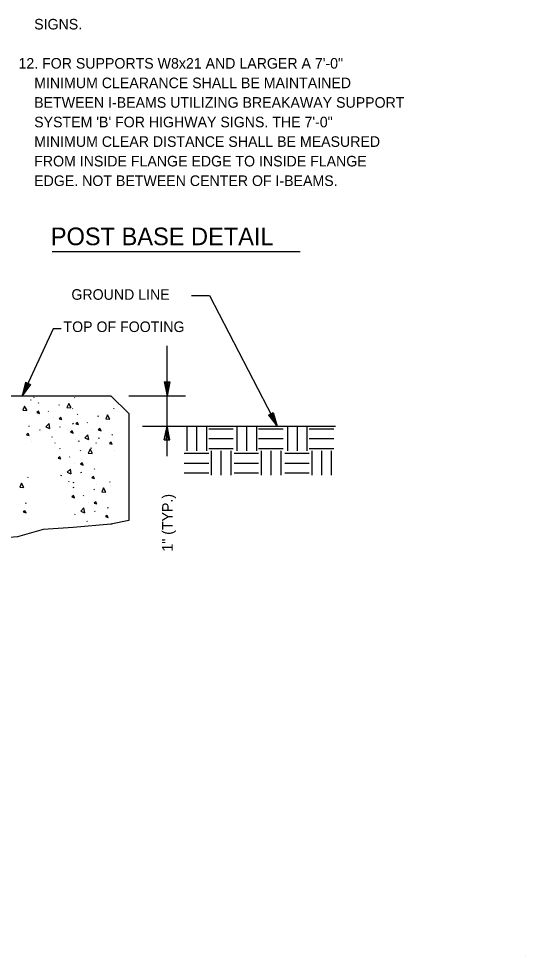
# Model space of a CAD drawing. Extents: x 12.3 to 19.6, y 18.8 to 29.6.
# Drawn here: x 16.75 to 19.62, y 19.32 to 24.63 of the extents above; entities that cross this region are included whole.
import ezdxf

# ---------------------------------------------------------------- set-up
doc = ezdxf.new("R2010")
doc.units = 0
for name, color, linetype in [('BORD-LINE', 7, 'Continuous'), ('DETL-DIMS', 7, 'Continuous'), ('DETL-LINE', 7, 'Continuous'), ('DETL-PATT', 7, 'Continuous'), ('DETL-TITL', 7, 'Continuous'), ('USER-BORD', 7, 'Continuous')]:
    doc.layers.add(name, color=color, linetype=linetype)

msp = doc.modelspace()

# ---------------------------------------------------------------- linework, layer by layer
at = {"layer": 'DETL-DIMS'}
for p, q in [((17.5901, 22.4922), (17.5901, 22.7757)), ((16.7869, 22.5695), (16.7676, 22.4922)), ((16.7676, 22.4922), (16.794, 22.5659)), ((16.8006, 22.5629), (16.7676, 22.4922)), ((16.7676, 22.4922), (16.8079, 22.5599)), ((16.815, 22.5563), (16.7676, 22.4922)), ((16.7869, 22.5695), (16.815, 22.5563)), ((17.5744, 22.5701), (17.6057, 22.5701)), ((17.5744, 22.5701), (17.5901, 22.4922)), ((17.5901, 22.4922), (17.5829, 22.5701)), ((17.5901, 22.5701), (17.5901, 22.4922)), ((17.6057, 22.5701), (17.5901, 22.4922)), ((17.5901, 22.4922), (17.5978, 22.5701)), ((17.3731, 22.4922), (17.6948, 22.4922)), ((17.5901, 22.3202), (17.5901, 22.4922)), ((18.1649, 22.3818), (18.1925, 22.3968)), ((18.1649, 22.3818), (18.2152, 22.3202)), ((18.2152, 22.3202), (18.1721, 22.3861)), ((18.1787, 22.3891), (18.2152, 22.3202)), ((18.2152, 22.3202), (18.1853, 22.3927)), ((18.1925, 22.3968), (18.2152, 22.3202)), ((17.5744, 22.241), (17.5901, 22.3189)), ((17.5901, 22.3189), (17.5829, 22.241)), ((17.5901, 22.1501), (17.5901, 22.3202)), ((17.5901, 22.241), (17.5901, 22.3189)), ((17.6057, 22.241), (17.5901, 22.3189)), ((17.5901, 22.3189), (17.5978, 22.241)), ((17.5744, 22.241), (17.6057, 22.241))]:
    msp.add_line(p, q, dxfattribs=at)
for points in [[(17.7279, 23.0602), (17.831, 23.0598), (18.2147, 22.3202)], [(16.9889, 22.8722), (16.9439, 22.8722), (16.7676, 22.4922)]]:
    msp.add_lwpolyline(points, dxfattribs=at)
at = {"layer": 'DETL-LINE'}
for p, q in [((16.5447, 22.4922), (17.2712, 22.4922)), ((17.3731, 22.3903), (17.2712, 22.4922)), ((17.3731, 22.3903), (17.3731, 21.7843)), ((17.4506, 22.3202), (18.5444, 22.3202)), ((17.3731, 21.7843), (17.2712, 21.7633))]:
    msp.add_line(p, q, dxfattribs=at)
for points in [[(17.2712, 21.7633), (17.0572, 21.7453), (16.8869, 21.7333), (16.7413, 21.6908), (16.5771, 21.6788), (16.4494, 21.7028), (16.2971, 21.7213), (16.0478, 21.7273), (15.817, 21.6968), (15.6527, 21.6601), (15.4339, 21.7028), (15.3489, 21.7519), (15.2451, 21.783)], [(17.279, 21.7627), (17.2712, 21.7633)]]:
    msp.add_lwpolyline(points, dxfattribs=at)
at = {"layer": 'DETL-PATT'}
for p, q in [((16.8342, 22.4837), (16.8324, 22.4808)), ((17.0674, 22.4826), (17.0649, 22.4796)), ((16.8174, 22.4682), (16.8156, 22.4652)), ((16.8636, 22.4472), (16.8611, 22.4514)), ((16.9793, 22.4358), (16.9774, 22.4406)), ((17.0554, 22.4202), (17.0536, 22.4172)), ((17.288, 22.4191), (17.2861, 22.4161)), ((16.9181, 22.4047), (16.9163, 22.4017)), ((16.9463, 22.3669), (16.9463, 22.3669)), ((17.0842, 22.3843), (17.0823, 22.3884)), ((17.2005, 22.3729), (17.1986, 22.3771)), ((16.809, 22.3177), (16.8072, 22.3219)), ((16.984, 22.3117), (16.9823, 22.3159)), ((17.0589, 22.3315), (17.0566, 22.3357)), ((17.1393, 22.3411), (17.1375, 22.3387)), ((17.7021, 22.3177), (17.7021, 22.1787)), ((17.7577, 22.3177), (17.7577, 22.1787)), ((17.8133, 22.3177), (17.8133, 22.1787)), ((17.9853, 22.3177), (17.9853, 22.1787)), ((18.0409, 22.3177), (18.0409, 22.1787)), ((18.0965, 22.3177), (18.0965, 22.1787)), ((18.2723, 22.3177), (18.2723, 22.1787)), ((18.3279, 22.3177), (18.3279, 22.1787)), ((18.3835, 22.3177), (18.3835, 22.1787)), ((16.8678, 22.2992), (16.8671, 22.2949)), ((16.9397, 22.2548), (16.9379, 22.259)), ((17.1675, 22.3033), (17.1675, 22.3033)), ((17.2801, 22.2685), (17.2777, 22.2728)), ((17.8262, 22.3048), (17.9652, 22.3048)), ((18.1094, 22.3048), (18.2483, 22.3048)), ((18.3964, 22.3048), (18.5353, 22.3048)), ((16.821, 22.2326), (16.821, 22.2326)), ((16.9553, 22.2254), (16.9535, 22.2224)), ((17.0704, 22.2464), (17.0704, 22.2464)), ((17.0889, 22.2362), (17.0883, 22.2314)), ((17.1885, 22.2242), (17.1861, 22.2213)), ((17.2052, 22.2482), (17.2035, 22.253)), ((17.8262, 22.2492), (17.9652, 22.2492)), ((18.1094, 22.2492), (18.2483, 22.2492)), ((18.3964, 22.2492), (18.5353, 22.2492)), ((16.9847, 22.1889), (16.9823, 22.1936)), ((17.1003, 22.178), (17.0986, 22.1823)), ((17.1608, 22.1913), (17.1591, 22.196)), ((17.2916, 22.1835), (17.2916, 22.1835)), ((17.6872, 22.1658), (17.8262, 22.1658)), ((17.8262, 22.1936), (17.9652, 22.1936)), ((17.8401, 22.1797), (17.8401, 22.0407)), ((17.8957, 22.1797), (17.8957, 22.0407)), ((17.9513, 22.1797), (17.9513, 22.0407)), ((17.9704, 22.1658), (18.1094, 22.1658)), ((18.1094, 22.1936), (18.2483, 22.1936)), ((18.1233, 22.1797), (18.1233, 22.0407)), ((18.1789, 22.1797), (18.1789, 22.0407)), ((18.2344, 22.1797), (18.2344, 22.0407)), ((18.2574, 22.1658), (18.3964, 22.1658)), ((18.3964, 22.1936), (18.5353, 22.1936)), ((18.4103, 22.1797), (18.4103, 22.0407)), ((18.4658, 22.1797), (18.4658, 22.0407)), ((18.5214, 22.1797), (18.5214, 22.0407)), ((17.0392, 22.1463), (17.0374, 22.1433)), ((17.0674, 22.1085), (17.0674, 22.1085)), ((17.6872, 22.1102), (17.8262, 22.1102)), ((17.9704, 22.1102), (18.1094, 22.1102)), ((18.2574, 22.1102), (18.3964, 22.1102)), ((17.1052, 22.0534), (17.1033, 22.0576)), ((17.1801, 22.0737), (17.1777, 22.078)), ((17.6872, 22.0546), (17.8262, 22.0546)), ((17.9704, 22.0546), (18.1094, 22.0546)), ((18.2574, 22.0546), (18.3964, 22.0546)), ((16.8, 22.03), (16.7982, 22.027)), ((16.9888, 22.0414), (16.9883, 22.0366)), ((17.0326, 22.0048), (17.0308, 22.0018)), ((17.0608, 21.9965), (17.0589, 22.0012)), ((17.2652, 22.0036), (17.2634, 22.0006)), ((17.0614, 21.9682), (17.0596, 21.9731)), ((17.1777, 21.9575), (17.1758, 21.9617)), ((17.1915, 21.9886), (17.1915, 21.9886)), ((17.1166, 21.9257), (17.1147, 21.9227)), ((17.1447, 21.8879), (17.1447, 21.8879)), ((16.7916, 21.8796), (16.7899, 21.8837)), ((17.1825, 21.8328), (17.1807, 21.837)), ((17.2568, 21.8532), (17.255, 21.8574)), ((16.803, 21.7944), (16.803, 21.7944)), ((17.0662, 21.8208), (17.0656, 21.816)), ((17.1381, 21.7759), (17.1363, 21.7807)), ((17.2687, 21.768), (17.2687, 21.768))]:
    msp.add_line(p, q, dxfattribs=at)
for points in [[(16.7959, 22.4088), (16.7826, 22.4334), (16.7725, 22.4107), (16.7952, 22.4088)], [(17.0458, 22.4226), (17.0326, 22.4478), (17.0218, 22.4244), (17.0452, 22.4226)], [(16.8665, 22.3921), (16.8611, 22.4041), (16.851, 22.3968), (16.8665, 22.3921)], [(16.9943, 22.3567), (16.9883, 22.3693), (16.9787, 22.3614), (16.9943, 22.3567)], [(17.2664, 22.3597), (17.2532, 22.3843), (17.243, 22.3614), (17.2664, 22.3597)], [(16.9247, 22.3063), (16.9211, 22.3345), (16.9031, 22.3165), (16.9241, 22.3063)], [(17.0878, 22.3285), (17.0818, 22.3411), (17.0722, 22.3333), (17.0878, 22.3285)], [(16.8084, 22.2662), (16.8024, 22.2782), (16.7929, 22.271), (16.8084, 22.2662)], [(17.0578, 22.2799), (17.0518, 22.2925), (17.0422, 22.2848), (17.0578, 22.2799)], [(17.1459, 22.2434), (17.1417, 22.271), (17.1243, 22.253), (17.1453, 22.2434)], [(17.2155, 22.2938), (17.2095, 22.3058), (17.1992, 22.2985), (17.2155, 22.2938)], [(17.279, 22.217), (17.273, 22.229), (17.2634, 22.2218), (17.279, 22.217)], [(17.1668, 22.1649), (17.1537, 22.1894), (17.1429, 22.1666), (17.1663, 22.1649)], [(16.9877, 22.1337), (16.9823, 22.1463), (16.972, 22.1385), (16.9877, 22.1337)], [(17.1153, 22.099), (17.1093, 22.1109), (17.0997, 22.1037), (17.1153, 22.099)], [(17.0458, 22.0486), (17.0422, 22.0761), (17.0242, 22.0582), (17.0452, 22.0486)], [(16.7785, 21.9707), (16.7652, 21.9952), (16.7551, 21.9725), (16.7779, 21.9707)], [(17.1788, 22.0222), (17.1728, 22.0342), (17.1633, 22.027), (17.1788, 22.0222)], [(17.2436, 21.9443), (17.2304, 21.9688), (17.2202, 21.9461), (17.2436, 21.9443)], [(17.2712, 21.9815), (17.2717, 21.9802)], [(17.0649, 21.9131), (17.0589, 21.9257), (17.0494, 21.9179), (17.0649, 21.9131)], [(17.1921, 21.8783), (17.1867, 21.8903), (17.1765, 21.8832), (17.1921, 21.8783)], [(16.7905, 21.828), (16.7845, 21.84), (16.7749, 21.8328), (16.7905, 21.828)], [(17.1231, 21.828), (17.1189, 21.8556), (17.1016, 21.8376), (17.1226, 21.828)], [(17.2562, 21.8017), (17.2502, 21.8136), (17.2406, 21.8064), (17.2562, 21.8017)]]:
    msp.add_lwpolyline(points, dxfattribs=at)
at = {"layer": 'DETL-TITL'}
msp.add_line((16.9394, 23.3109), (18.3457, 23.3109), dxfattribs=at)
at = {"layer": 'USER-BORD'}
msp.add_line((19.6215, 19.3182), (19.6215, 19.3182), dxfattribs=at)

# ---------------------------------------------------------------- texts
at = {"layer": 'BORD-LINE'}
for s, p in [('    SIGNS.', (16.7475, 24.5696)), ('12. FOR SUPPORTS W8x21 AND LARGER A 7\'-0"', (16.7475, 24.3476)), ('    MINIMUM CLEARANCE SHALL BE MAINTAINED', (16.7475, 24.2366)), ('    BETWEEN I-BEAMS UTILIZING BREAKAWAY SUPPORT ', (16.7475, 24.1256)), ('    SYSTEM \'B\' FOR HIGHWAY SIGNS. THE 7\'-0" ', (16.7475, 24.0146)), ('    MINIMUM CLEAR DISTANCE SHALL BE MEASURED ', (16.7475, 23.9036)), ('    FROM INSIDE FLANGE EDGE TO INSIDE FLANGE ', (16.7475, 23.7926)), ('    EDGE. NOT BETWEEN CENTER OF I-BEAMS. ', (16.7475, 23.6816)), ('GROUND LINE', (17.0477, 23.0363)), ('TOP OF FOOTING', (17.0028, 22.8534))]:
    msp.add_text(s, height=0.06, dxfattribs=at).set_placement(p)
msp.add_text('1" (TYP.)', height=0.06, rotation=90, dxfattribs=at).set_placement((17.6222, 21.6078))
at = {"layer": 'DETL-TITL'}
msp.add_text('POST BASE DETAIL', height=0.1, dxfattribs=at).set_placement((16.9309, 23.3459))

doc.saveas('drawing.dxf')
